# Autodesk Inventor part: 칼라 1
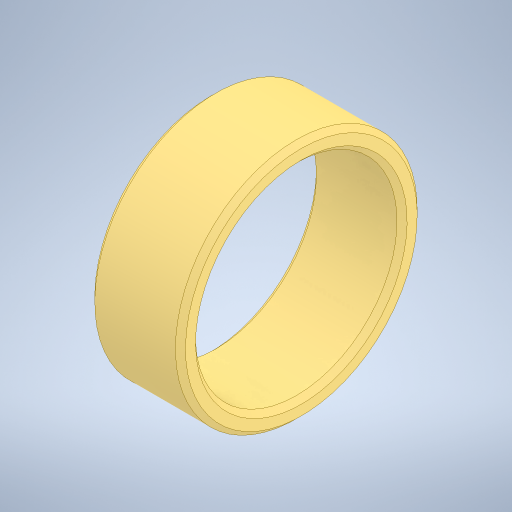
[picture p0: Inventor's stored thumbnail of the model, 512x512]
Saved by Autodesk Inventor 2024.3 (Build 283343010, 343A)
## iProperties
Created: 2025-11
Part Number: 칼라 1
Material: 강철, 연강
Document SubType Name: Modeling
Designer: PC2-15
Density: 7.85 g/cm^3
Appearance: 기본값
Author: jhkim
Sending System: Autodesk Inventor 2026
Preprocessor: ST-DEVELOPER v20.1
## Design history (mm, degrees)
node "칼라 11"
node "솔리드2"
node "솔리드1"
